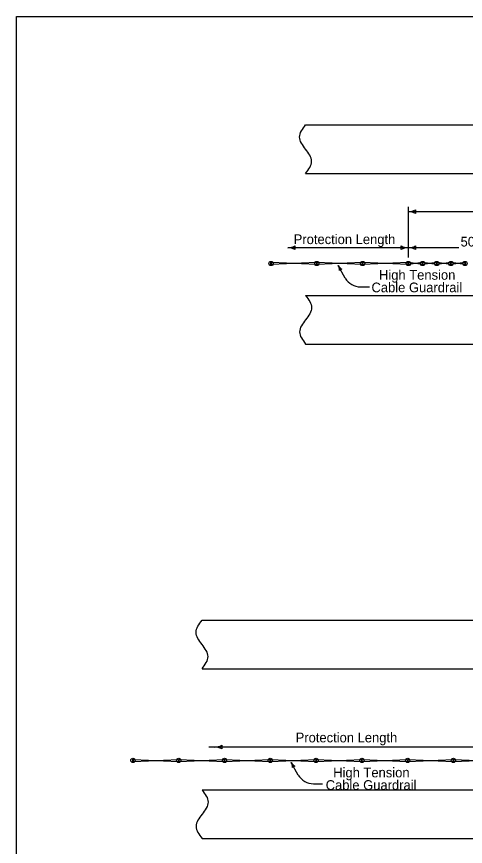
# Model space of a CAD drawing. Extents: x 10133 to 81668, y 7924 to 11018.
# Drawn here: x 10133 to 10688, y 8918 to 9944 of the extents above; entities that cross this region are included whole.
import ezdxf

# ---------------------------------------------------------------- set-up
doc = ezdxf.new("R2010")
doc.units = 0
for name, color, linetype in [('dsnCellElements', 7, 'Continuous'), ('DsnShtRevisedText', 7, 'Continuous'), ('dsnStdDimension', 7, 'Continuous'), ('SheetBorder', 7, 'Continuous')]:
    doc.layers.add(name, color=color, linetype=linetype)

msp = doc.modelspace()

# ---------------------------------------------------------------- linework, layer by layer
at = {"layer": 'dsnCellElements'}
for p, q in [((10503.8, 9639.7), (10448, 9637.5)), ((10503.8, 9637.5), (10448, 9639.7)), ((10560.5, 9639.7), (10504.7, 9637.5)), ((10560.5, 9637.5), (10504.7, 9639.7)), ((10617.2, 9639.7), (10561.4, 9637.5)), ((10617.2, 9637.5), (10561.4, 9639.7)), ((10634.8, 9639.7), (10618.1, 9637.5)), ((10634.8, 9637.5), (10618.1, 9639.7)), ((10652.3, 9639.7), (10635.7, 9637.5)), ((10652.3, 9637.5), (10635.7, 9639.7)), ((10669.9, 9639.7), (10653.2, 9637.5)), ((10669.9, 9637.5), (10653.2, 9639.7)), ((10687.4, 9639.7), (10670.8, 9637.5)), ((10687.4, 9637.5), (10670.8, 9639.7)), ((10277.1, 9022.7), (10332.9, 9024.9)), ((10277.1, 9024.9), (10332.9, 9022.7)), ((10333.8, 9022.7), (10389.6, 9024.9)), ((10333.8, 9024.9), (10389.6, 9022.7)), ((10390.5, 9022.7), (10446.3, 9024.9)), ((10390.5, 9024.9), (10446.3, 9022.7)), ((10447.2, 9022.7), (10503, 9024.9)), ((10447.2, 9024.9), (10503, 9022.7)), ((10503.9, 9022.7), (10559.7, 9024.9)), ((10503.9, 9024.9), (10559.7, 9022.7)), ((10560.6, 9022.7), (10616.4, 9024.9)), ((10560.6, 9024.9), (10616.4, 9022.7)), ((10617.3, 9022.7), (10673.1, 9024.9)), ((10617.3, 9024.9), (10673.1, 9022.7)), ((10674, 9022.7), (10729.8, 9024.9)), ((10674, 9024.9), (10729.8, 9022.7))]:
    msp.add_line(p, q, dxfattribs=at)
for points in [[(10448, 9637.5), (10448, 9639.7), (10447.1, 9639.7), (10447.1, 9637.5)], [(10504.7, 9637.5), (10504.7, 9639.7), (10503.8, 9639.7), (10503.8, 9637.5)], [(10504.7, 9637.5), (10504.7, 9639.7), (10503.8, 9639.7), (10503.8, 9637.5)], [(10561.4, 9637.5), (10561.4, 9639.7), (10560.5, 9639.7), (10560.5, 9637.5)], [(10561.4, 9637.5), (10561.4, 9639.7), (10560.5, 9639.7), (10560.5, 9637.5)], [(10618.1, 9637.5), (10618.1, 9639.7), (10617.2, 9639.7), (10617.2, 9637.5)], [(10618.1, 9637.5), (10618.1, 9639.7), (10617.2, 9639.7), (10617.2, 9637.5)], [(10635.7, 9637.5), (10635.7, 9639.7), (10634.8, 9639.7), (10634.8, 9637.5)], [(10653.2, 9637.5), (10653.2, 9639.7), (10652.3, 9639.7), (10652.3, 9637.5)], [(10670.8, 9637.5), (10670.8, 9639.7), (10669.9, 9639.7), (10669.9, 9637.5)], [(10688.3, 9637.5), (10688.3, 9639.7), (10687.4, 9639.7), (10687.4, 9637.5)], [(10276.2, 9024.9), (10276.2, 9022.7), (10277.1, 9022.7), (10277.1, 9024.9)], [(10332.9, 9024.9), (10332.9, 9022.7), (10333.8, 9022.7), (10333.8, 9024.9)], [(10332.9, 9024.9), (10332.9, 9022.7), (10333.8, 9022.7), (10333.8, 9024.9)], [(10389.6, 9024.9), (10389.6, 9022.7), (10390.5, 9022.7), (10390.5, 9024.9)], [(10389.6, 9024.9), (10389.6, 9022.7), (10390.5, 9022.7), (10390.5, 9024.9)], [(10446.3, 9024.9), (10446.3, 9022.7), (10447.2, 9022.7), (10447.2, 9024.9)], [(10446.3, 9024.9), (10446.3, 9022.7), (10447.2, 9022.7), (10447.2, 9024.9)], [(10503, 9024.9), (10503, 9022.7), (10503.9, 9022.7), (10503.9, 9024.9)], [(10503, 9024.9), (10503, 9022.7), (10503.9, 9022.7), (10503.9, 9024.9)], [(10559.7, 9024.9), (10559.7, 9022.7), (10560.6, 9022.7), (10560.6, 9024.9)], [(10559.7, 9024.9), (10559.7, 9022.7), (10560.6, 9022.7), (10560.6, 9024.9)], [(10616.4, 9024.9), (10616.4, 9022.7), (10617.3, 9022.7), (10617.3, 9024.9)], [(10616.4, 9024.9), (10616.4, 9022.7), (10617.3, 9022.7), (10617.3, 9024.9)], [(10673.1, 9024.9), (10673.1, 9022.7), (10674, 9022.7), (10674, 9024.9)], [(10673.1, 9024.9), (10673.1, 9022.7), (10674, 9022.7), (10674, 9024.9)]]:
    msp.add_lwpolyline(points, close=True, dxfattribs=at)
for centre in [(10447.6, 9638.6), (10504.3, 9638.6), (10504.3, 9638.6), (10561, 9638.6), (10561, 9638.6), (10617.7, 9638.6), (10617.7, 9638.6), (10635.2, 9638.6), (10652.8, 9638.6), (10670.3, 9638.6), (10687.8, 9638.6), (10276.6, 9023.8), (10333.3, 9023.8), (10333.3, 9023.8), (10390, 9023.8), (10390, 9023.8), (10446.7, 9023.8), (10446.7, 9023.8), (10503.4, 9023.8), (10503.4, 9023.8), (10560.1, 9023.8), (10560.1, 9023.8), (10616.8, 9023.8), (10616.8, 9023.8), (10673.5, 9023.8), (10673.5, 9023.8)]:
    msp.add_circle(centre, 2.66, dxfattribs=at)
at = {"layer": 'DsnShtRevisedText'}
for p, q in [((10617.7, 9646.1), (10617.7, 9708.7)), ((10940.6, 9702.7), (10617.7, 9702.7)), ((10595, 9658.1), (10468.3, 9658.1)), ((10617.7, 9658.1), (10595, 9658.1)), ((10680.3, 9658.1), (10617.7, 9658.1)), ((10539.6, 9620.6), (10530.7, 9636.2)), ((10558.4, 9609.8), (10569.7, 9609.8)), ((10572.8, 9040.4), (10370.4, 9040.4)), ((10787.1, 9040.4), (10572.8, 9040.4)), ((10481.3, 9005.8), (10472.5, 9021.5)), ((10500.2, 8995), (10511.4, 8995))]:
    msp.add_line(p, q, dxfattribs=at)
for centre, radius, start, end in [((10617.7, 9721.9), 19.1, 270, 298.0725), ((10617.7, 9683.6), 19.1, 61.9275, 90), ((10633.7, 9702.7), 7.39, 162.2666, 197.7334), ((10468.3, 9677.2), 19.1, 270, 298.0725), ((10484.3, 9658.1), 7.39, 162.2666, 197.7334), ((10601.6, 9658.1), 7.39, 342.2666, 17.7333), ((10617.7, 9677.2), 19.1, 241.9275, 270), ((10617.7, 9677.2), 19.1, 270, 298.0725), ((10633.7, 9658.1), 7.39, 162.2666, 197.7334), ((10468.3, 9639), 19.1, 61.9275, 90), ((10617.7, 9639), 19.1, 90, 118.0725), ((10617.7, 9639), 19.1, 61.9275, 90), ((10519, 9629.4), 13.6, 2.1589, 30.2314), ((10542.5, 9643.1), 13.6, 210.2314, 238.3038), ((10536.5, 9626.4), 5.25, 102.498, 137.9647), ((10558.4, 9631.5), 21.8, 210.2243, 270), ((10377.7, 9059.5), 19.1, 270, 298.0725), ((10377.7, 9021.2), 19.1, 61.9275, 90), ((10393.8, 9040.4), 7.39, 162.2666, 197.7334), ((10460.7, 9014.6), 13.6, 2.1589, 30.2314), ((10484.2, 9028.3), 13.6, 210.2314, 238.3038), ((10478.2, 9011.6), 5.25, 102.498, 137.9647), ((10500.2, 9016.8), 21.8, 210.2243, 270)]:
    msp.add_arc(centre, radius, start, end, dxfattribs=at)
at = {"layer": 'dsnStdDimension'}
for p, q in [((10490.4, 9810), (11366, 9810)), ((10490.4, 9750), (11366, 9750)), ((10490.4, 9599), (11366, 9599)), ((10490.4, 9539), (11366, 9539)), ((10362.2, 9197.3), (11477.9, 9197.3)), ((10362.2, 9137.3), (11477.9, 9137.3)), ((10362.2, 8987.3), (11477.9, 8987.3)), ((10362.2, 8927.3), (11477.9, 8927.3))]:
    msp.add_line(p, q, dxfattribs=at)
for points in [[(10490.4, 9750), (10497.9, 9765), (10490.4, 9780), (10482.9, 9795), (10490.4, 9810)], [(10490.4, 9599), (10497.9, 9584), (10490.4, 9569), (10482.9, 9554), (10490.4, 9539)], [(10362.2, 9137.3), (10369.7, 9152.3), (10362.2, 9167.3), (10354.7, 9182.3), (10362.2, 9197.3)], [(10362.2, 8987.3), (10369.7, 8972.3), (10362.2, 8957.3), (10354.7, 8942.3), (10362.2, 8927.3)]]:
    msp.add_spline(points, degree=3, dxfattribs=at)
at = {"layer": 'SheetBorder'}
msp.add_lwpolyline([(10132.5, 9944), (13267.5, 9944), (13267.5, 7924), (10132.5, 7924)], close=True, dxfattribs=at)

# ---------------------------------------------------------------- texts
at = {"layer": 'DsnShtRevisedText'}
for s, p in [('Protection Length', (10475.7, 9662.6)), ("50' End Anchor", (10682.3, 9659.6)), ('High Tension', (10581.3, 9618.5)), ('Cable Guardrail', (10572, 9603)), ('Protection Length', (10478.1, 9046.2)), ('High Tension', (10524.6, 9002.9)), ('Cable Guardrail', (10515.3, 8987.4))]:
    msp.add_text(s, height=12, dxfattribs=at).set_placement(p)

doc.saveas('drawing.dxf')
